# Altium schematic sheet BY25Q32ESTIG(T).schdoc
size 127 x 101 mm
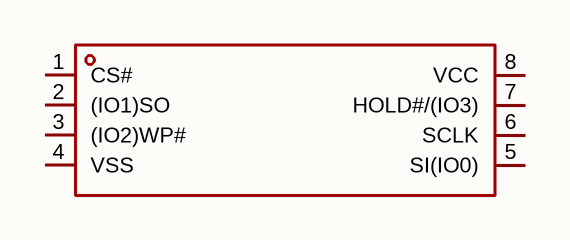
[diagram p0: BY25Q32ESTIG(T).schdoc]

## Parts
U?  by25q32estig(t)  [SOP-8_L4.9-W3.9-P1.27-LS6.0-BL]  (value not drawn)

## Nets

Not connected (* = marked no-connect by the designer): U? 1(CS#) 2((IO1)SO) 3((IO2)WP#) 4(VSS) 5(SI(IO0)) 6(SCLK) 7(HOLD#/(IO3)) 8(VCC)

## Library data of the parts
U? = by25q32estig(t): 接口类型:SPI;存储容量:32Mbit;时钟频率(fc):120MHz;; Manufacturer: BOYAMICRO(博雅); AddInBom: yes; ModelId: 75c24a7891ee4dd6bdac16a7163ff87e; ModelName: SOP-8_L4.9-W3.9-P1.27-LS6.0-BL-1; ModelTransform: 192.913,236.22,0,0,0,0,-0.393,2.749,0; Interface: SPI; Memory Size: 32Mbit; Clock Frequency: 120MHz; Voltage - Supply: 2.7V~3.6V; Standby Supply Current: 2uA; Program / Erase Cycles: 100000次; Page Programming Time (Tpp): 450us; Block Erase Time(tBE): 180ms@64KB; Data Retention - TDR (Year): 20年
